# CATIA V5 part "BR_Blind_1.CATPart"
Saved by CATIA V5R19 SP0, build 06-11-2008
Bounding box of the stored display mesh (mm): x 26.985 to 40.967, y -59.09 to -45.3, z -22.887 to 0
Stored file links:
  C:\Program Files\Dassault Systemes\Power Feature\SampleData\SharedData\BusinessRules\BR_RulesPart\BR_Blind_1.CATPart
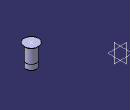
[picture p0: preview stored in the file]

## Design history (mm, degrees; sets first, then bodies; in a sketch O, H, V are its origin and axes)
Set1
  Point1: type OnPlane, Support xy-plane, Direction (1, 0, 0), H 33.976, V -52.195
Body1 (main body)
  UdfFeature1 "Blind Hole": UdfInputSpec1 AxisSystem1, DB 10, T 20, F 2, W 90, SW 120, DP 0, TP 15, AS_H 0, AS_D 0, InternalVersion 1, Through false, Threaded false, UIHidden_zDB 5 {= Body2.DB / 2}, UIHidden_zF 2, UIHidden_zTP 15
Body2 "UDF_Body"
  AxisSystem1 "MainAxisSystem": origin (33.976, -52.195, 0), X (-1, 0, 0), Y (0, -1, 0), Z (0, 0, 1)
  Sketch1 "MainProfileSketch" on ZX plane of AxisSystem1, origin (33.976, -52.195, 0), H (1, 0, 0), V (0, 0, 1)
    axis line L1 (0, 0) -> (0, -22.8868)
    point P2 (0, -22.8868)
    line L2 (0, -22.8868) -> (5, -20)
    point P3 (5, -20)
    line L3 (5, -20) -> (5, -15)
    line L4 (5, -2) -> (7, 0)
    point P4 (7, 0)
    line L5 (7, 0) -> (7, 0)
    line L6 (7, 0) -> (7, 0)
    line L7 (7, 0) -> (0, 0)
    point P7 (-5, -20)
    point P8 (0, -22.8868)
    construction line L8 (0, -22.8868) -> (-5, -20)
    construction line L9 (7, 0) -> (0, 0)
    reference projected line E1 through (0, 0) direction (-1, 0) from edge [XY plane of AxisSystem1 | ZX plane of AxisSystem1]
    reference projected line E2 through (0, 0) direction (-1, 0) from edge [XY plane of AxisSystem1 | ZX plane of AxisSystem1]
    reference projected line E3 through (0, 0) direction (0, 1) from edge [ZX plane of AxisSystem1 | YZ plane of AxisSystem1]
    point P9 (5, -15)
    reference projected line E4 through (0, 0) direction (-1, 0) from edge [XY plane of AxisSystem1 | ZX plane of AxisSystem1]
    point P10 (5, -2)
    point P11 (-7, 0)
    point P12 (-5, -2)
    construction line L10 (-5, -2) -> (-7, 0)
    line L11 (5, -15) -> (5, -2)
    reference projected line E5 through (0, 0) direction (-1, 0) from edge [XY plane of AxisSystem1 | ZX plane of AxisSystem1]
    point P13 (5, -2)
    reference projected line E6 through (0, 0) direction (-1, 0) from edge [XY plane of AxisSystem1 | ZX plane of AxisSystem1]
    point P14 (0, 30)
    point P15 (5, 25)
    point P16 (5, -15)
    point P17 (5, -15)
    line L12 (5, -15) -> (5, -15)
    angle L4 L10 = 90
    angle L2 L8 = 120
    distance E1 P3 = 20
    length L9 = 7 {= sqrt((Body2.AS_H * Body2.AS_H ) + ((Groove1.top_width / 2 + Groove1.AS_ZR ) * (Groove1.top_width / 2 + Groove1.AS_ZR )))}
    angle L9 L5 = 0 {= atan(Body2.AS_H / (Groove1.top_width / 2 + Groove1.AS_ZR ))}
    distance E4 P17 = 15
    "UIHidden_zDB" L11 L1 = 5 {= Body2.DB / 2}
    distance E6 P10 = 2
    distance O P14 = 30
    distance P10 P14 V = 32 {= Sketch1.distance(O P14) + Body2.F}
    distance O P15 V = 25
    distance P16 P15 = 40
    distance P9 P15 = 40
    distance P17 P15 = 40 {= Sketch1.distance(O P15 V) + Body2.TP}
    "Radius" L3 L1 = 5 {= Sketch1.UIHidden_zDB(L11 L1)}
    coincidence: E5 L5, L1 E3, P13 L11, P13 P10, P14 L1, P15 L11, P17 L11
    symmetry: P3 P7 L1, P2 P8 L1, L2 L8 L1, P4 P11 L1, P10 P12 L1, L4 L10 L1
    perpendicularity: L1 L7, E2 L6
  Groove1 "MainGroove": profile Sketch1, axis Sketch1.L1, angle 360
Relations
  Body2.W = Sketch1.angle(L4 L10)
  Body2.T = Sketch1.distance(E1 P3)
  Body2.SW = Sketch1.angle(L2 L8)
  Groove1.top_width = (Sketch1.UIHidden_zDB(L11 L1) * 2) + (2 * tan(Sketch1.angle(L4 L10) / 2) *Sketch1.distance(E6 P10))
  rule "AS_ZR":
    /*Rule created by AKNOPP 22.05.2006*/
    Groove1.AS_ZR = Body2.AS_D - Groove1.top_width
    if (Body2.AS_D == 0mm)
    {
    	Groove1.AS_ZR = 0mm
    }
    else
    {
    	Groove1.AS_ZR = (Body2.AS_D / 2) - (Groove1.top_width / 2)
    }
